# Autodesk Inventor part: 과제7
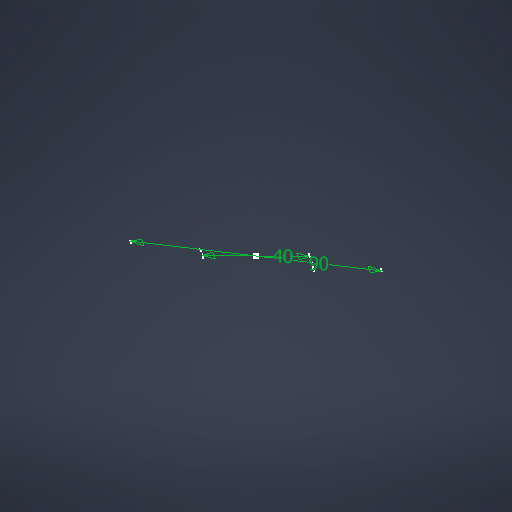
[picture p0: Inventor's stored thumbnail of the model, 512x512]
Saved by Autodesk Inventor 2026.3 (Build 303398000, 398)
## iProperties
Created: 2026-08
Part Number: 과제7
Material: 일반
Document SubType Name: Modeling
Designer: PC User
Density: 1 g/cm^3
Appearance: 기본값
Author: PC User
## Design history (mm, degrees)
sketch "스케치1"
  geometry: C1 r 20 at (0, 0); C2 r 45 at (0, 0); 1 further point
  constraints: 2 centre point, 2 coincident
  dimensions: "d16" = 40 dimension on point (0, 0) C1.centre C1 C2.centre C2; "d16" = 40 diameter of C1; "d17" = 90 diameter of C2
